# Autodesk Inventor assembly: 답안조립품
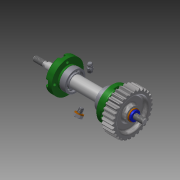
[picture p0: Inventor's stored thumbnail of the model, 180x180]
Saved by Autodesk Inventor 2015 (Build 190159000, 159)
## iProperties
Created: 2015-11
Part Number: 답안조립품
Document SubType Name: Assembly
Designer: Administrator
Author: Administrator
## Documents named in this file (13)
- C:\Users\Administrator\Desktop\451109V1037\답안조립품.iam
- C:\Users\Administrator\Desktop\451109V1037\1.본체.ipt
- C:\Users\Administrator\Desktop\451109V1037\와셔 6x11.5.ipt
- C:\Users\Administrator\Desktop\451109V1037\볼트 M 6 x 8.ipt
- C:\Users\Administrator\Desktop\451109V1037\니플 M 6 x 0.75.ipt
- C:\Users\Administrator\Desktop\451109V1037\베어링 15 x 32 x 9.ipt
- C:\Users\Administrator\Desktop\451109V1037\커버.ipt
- C:\Users\Administrator\Desktop\451109V1037\오일 실 15 25 7.ipt
- C:\Users\Administrator\Desktop\451109V1037\축.ipt
- C:\Users\Administrator\Desktop\451109V1037\스퍼기어.ipt
- C:\Users\Administrator\Desktop\451109V1037\키 3 x 3 x 12.ipt
- C:\Users\Administrator\Desktop\451109V1037\와셔 8x17.ipt
- C:\Users\Administrator\Desktop\451109V1037\스프링와셔 8.ipt
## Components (3 placed, 2 different names)
1. 1.본체:1 — 각도:1, 각도:2
2. KS B 2023 6002 - 15 x 32 x 9:1
3. KS B 2023 6002 - 15 x 32 x 9:2
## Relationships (2: Angle 2)
- 각도:1 [Angle]: 1.본체:1
- 각도:2 [Angle]: 1.본체:1
